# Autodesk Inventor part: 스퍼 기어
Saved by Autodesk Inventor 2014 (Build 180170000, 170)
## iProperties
Created: 2026-04
Part Number: 스퍼 기어
Material: 일반
Document SubType Name: Modeling
Designer: dg
Density: 1 g/cm^3
Appearance: 기본값
Author: dg
Author: jhkim
Creation Date: 2026-03-26
Sending System: Autodesk Inventor 2026
Preprocessor: ST-DEVELOPER v20.1
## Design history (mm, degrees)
node "스퍼 기어1"
node "솔리드1"
node "기준1"
